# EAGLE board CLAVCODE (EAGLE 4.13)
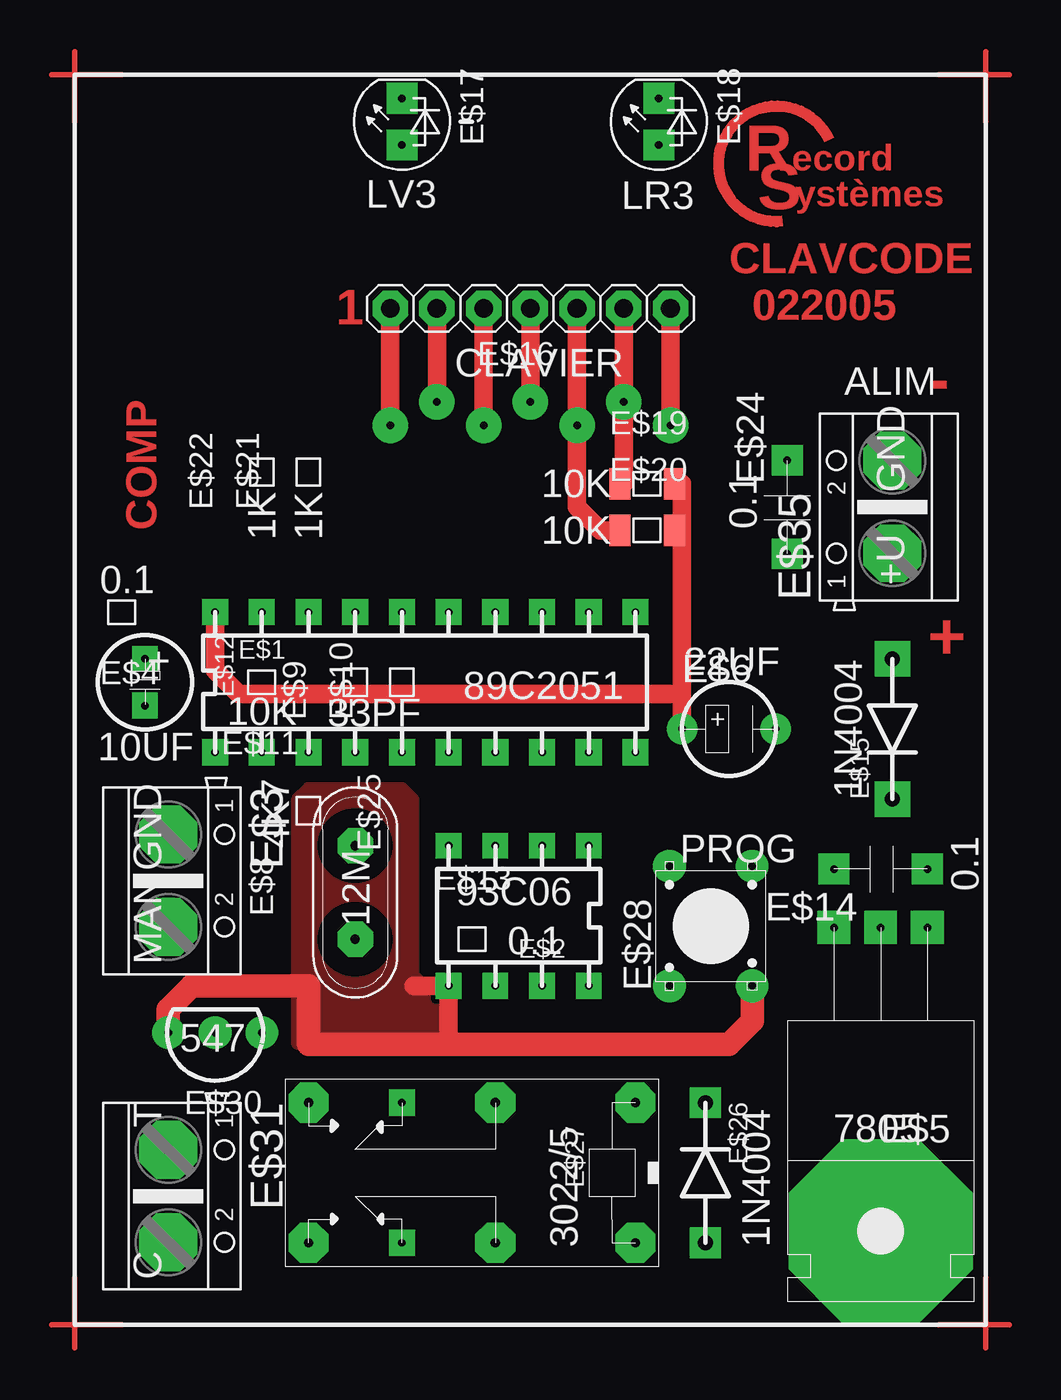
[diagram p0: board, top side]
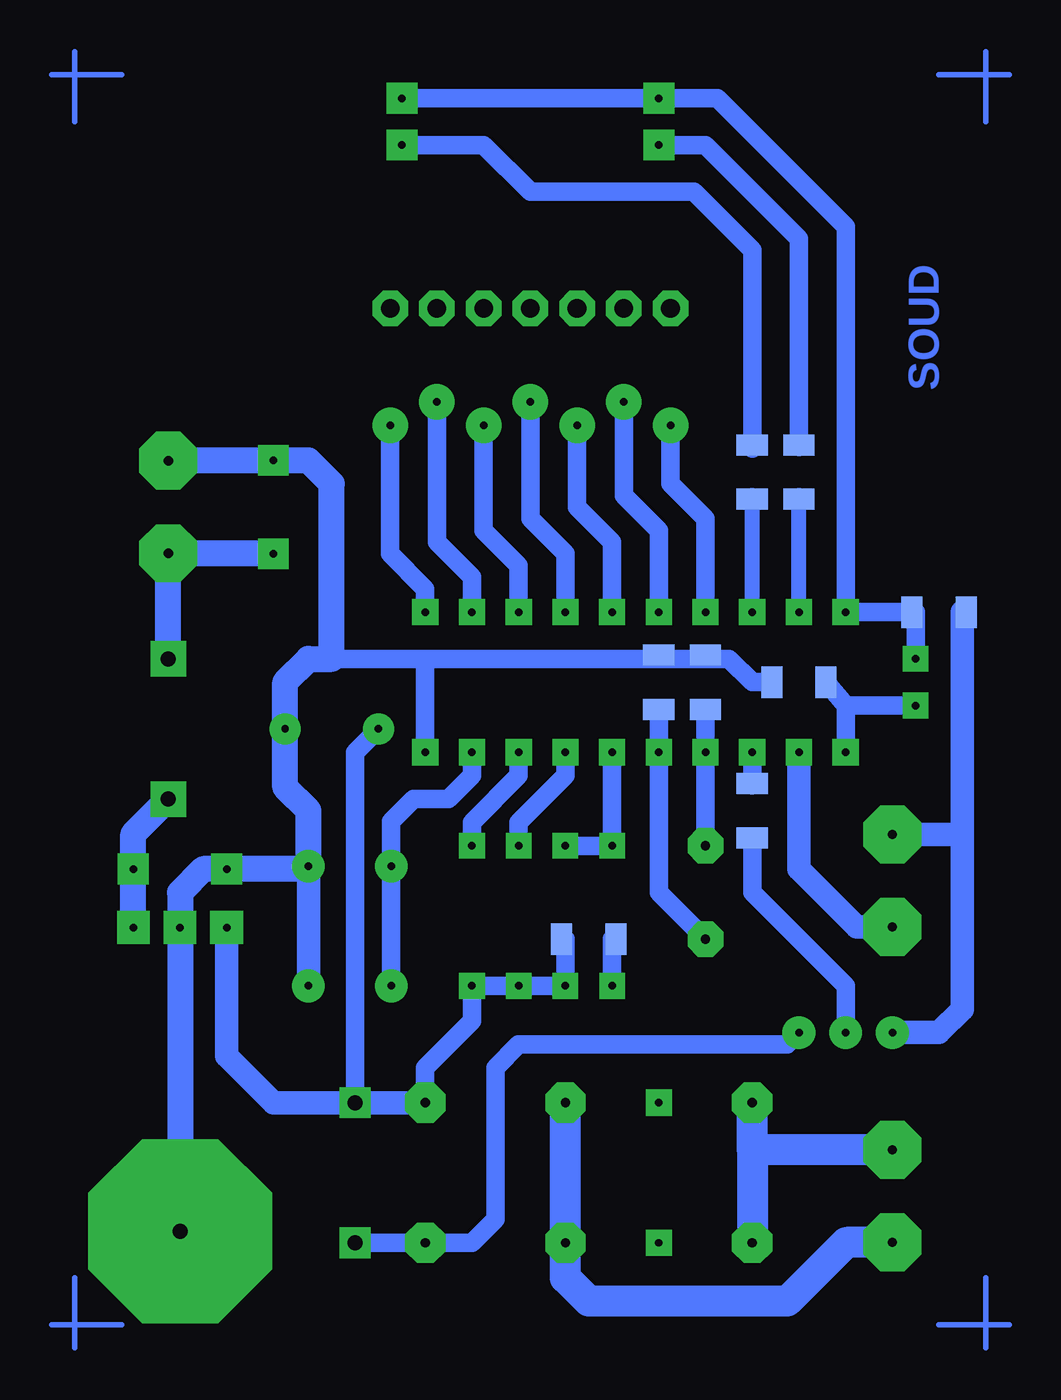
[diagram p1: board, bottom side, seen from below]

No outline drawn. Coordinates in mm, seen from the top.
Copper layers (1*16): Top 0.035mm / dielectric 1.5mm / Bottom 0.035mm
Design rules "default": minimum track width 0.3mm, minimum drill 0.4mm, track to track 0.1mm, track to pad 0.1mm, pad to pad 0.1mm, via to via 0.1mm, smd to smd 0.1mm, copper to edge 0.1mm, drill to drill 0.1mm, minimum pad ring 10mil, minimum via ring 8mil, stop-mask expansion 0mil, vias tented up to drill 0mil, thermal gap 10mil
Net classes: 0 signal: width 0.4 mm, drill 0.4 mm, clearance 0.4 mm; 1 siggros: width 0.8 mm, drill 0.6 mm, clearance 0.4 mm; 2 alim: width 1 mm, drill 1 mm, clearance 0.4 mm; 3 alimgros: width 1.27 mm, drill 1 mm, clearance 0.4 mm
tRestrict: area 13.3,24.1 to 17.1,27.9; area 13.3,19 to 17.1,22.9

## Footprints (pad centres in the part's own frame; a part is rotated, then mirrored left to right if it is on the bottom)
DIL20 = drill 0.406 pad 1.422 square: 1 0,0; 2 2.54,0; 3 5.08,0; 4 7.62,0; 5 10.16,0; 6 12.7,0; 7 15.24,0; 8 17.78,0; 9 20.32,0; 10 22.86,0; 11 22.86,7.62; 12 20.32,7.62; 13 17.78,7.62; 14 15.24,7.62; 15 12.7,7.62; 16 10.16,7.62; 17 7.62,7.62; 18 5.08,7.62; 19 2.54,7.62; 20 0,7.62
DIL8 = drill 0.406 pad 1.397 square: 1 0,0; 2 2.54,0; 3 5.08,0; 4 7.62,0; 5 7.62,7.62; 6 5.08,7.62; 7 2.54,7.62; 8 0,7.62
AK500/2 = drill 0.5 pad 3.15 octagon: 1 -2.515,0; 2 2.515,0
1206CU = smd 1.143 x 1.702 bottom: 1 -1.473,0; 2 1.473,0
78X = drill 0.406 pad 1.778 square: 1 0,0; 2 2.54,0; 3 5.08,0 | drill 0.813 pad 6.452 round: FIX 2.54,16.51
E5 = drill 0.406 pad 1.676 round: + 0,0; - 5.08,0
QS = drill 0.406 pad 1.676 octagon: 1 0,0; 2 5.08,0
E2,5 = drill 0.406 pad 1.397 square: + 0,0; - 2.54,0
C5 = drill 0.406 pad 1.676 square: 1 0,0; 2 5.08,0
D7,5 = drill 0.813 pad 1.676 square: A 7.62,0; K 0,0
1X07 = drill 1.016 pad 1.676 octagon: 1 -7.62,0; 2 -5.08,0; 3 -2.54,0; 4 0,0; 5 2.54,0; 6 5.08,0; 7 7.62,0
LED5VERT = drill 0.406 pad 1.676 square: A 0,0; K 0,2.54
1206 = smd 1.143 x 1.702: 1 -1.473,0; 2 1.473,0
OMRON = drill 0.406 pad 1.422 square: 1 0,0; 4 7.62,0; 6 12.7,0; 8 17.78,0; 9 17.78,7.62; 11 12.7,7.62; 13 7.62,7.62; 16 0,7.62
SECHOR = drill 0.406 pad 1.778 round: 1 0,0; 2 6.5,0; 3 6.5,4.5; 4 0,4.5
T1 = drill 0.406 pad 1.778 round: B 0,2.54; C 0,5.08; E 0,0

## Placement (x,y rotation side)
E$1  [DIL20]  7.62,31.11 0 top
E$2  [DIL8]  27.94,26.04 180 top
E$3  [AK500/2]  5.08,24.13 270 top
E$4  [1206CU]  2.54,38.73 180 top
E$5  [78X]  46.35,21.59 180 top
E$6  [E5]  33.02,32.38 0 top
E$7  [CORNER2]  0,0 180 top
E$8  [QS]  15.24,20.95 90 top
E$9  [1206CU]  15.24,34.92 90 top
E$10  [1206CU]  17.78,34.92 90 top
E$11  [1206CU]  10.16,34.92 180 top
E$12  [E2,5]  3.81,36.2 270 top
E$13  [1206CU]  21.59,20.95 0 top
E$14  [C5]  46.35,24.77 180 top
E$15  [D7,5]  44.45,28.57 90 top
E$16  [1X07]  24.77,55.24 180 top
E$17  [LED5VERT]  17.78,64.14 0 top
E$18  [LED5VERT]  31.75,64.14 0 top
E$19  [1206]  31.11,45.72 0 top
E$20  [1206]  31.11,43.18 0 top
E$21  [1206CU]  12.7,46.35 90 top
E$22  [1206CU]  10.16,46.35 90 top
E$23  [PRSCOMP]  47.62,60.96 0 top
E$24  [C5]  38.73,41.91 90 top
E$25  [1206CU]  12.7,27.94 270 top
E$26  [D7,5]  34.29,12.06 270 top
E$27  [OMRON]  30.48,12.06 180 top
E$28  [SECHOR]  36.83,18.41 90 top
E$29  [CORNER2]  49.53,0 270 top
E$30  [T1]  5.08,15.88 270 top
E$31  [AK500/2]  5.08,6.99 270 top
E$32  [CORNER2]  49.53,67.94 0 top
E$33  [CORNER2]  0,67.94 90 top
E$35  [AK500/2]  44.45,44.45 90 top

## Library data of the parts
E$1 E$2 E$5 E$6 E$8 E$12 E$14 E$15 E$17 E$18 E$23 E$24 E$26 E$27 E$30 = RECORD
E$3 E$31 E$35 = PTR500
E$4 E$9-E$11 E$13 E$19-E$22 E$25 = SMD
E$7 E$29 E$32 E$33 = MARKS
E$16 = PINHEAD
E$28 = KEY

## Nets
+5: E$1.20 E$2.6 E$2.7 E$2.8 E$4.1 E$5.3 E$6.+ E$12.+ E$13.2 E$17.K E$18.K E$19.2 E$20.2 E$26.K E$27.1
GND: E$1.10 E$2.5 E$3.1 E$4.2 E$5.2 E$5.FIX E$6.- E$9.2 E$10.2 E$11.1 E$13.1 E$14.2 E$24.2 E$28.1 E$28.2 E$30.E E$35.2
RST: E$1.1 E$11.2 E$12.-
S$1: E$1.4 E$8.2 E$9.1
S$2: E$1.5 E$8.1 E$10.1
S$3: E$1.2 E$3.2
S$6: E$1.6 E$2.3 E$2.4
S$7: E$1.7 E$2.2
S$8: E$1.8 E$2.1
S$9 [alimgros]: E$15.A E$24.1 E$35.1
S$12: E$1.17 E$16.7
S$13: E$1.16 E$16.6
S$14: E$1.15 E$16.5
S$15: E$1.14 E$16.4
S$16: E$1.13 E$16.3 E$20.1
S$17: E$1.12 E$16.2 E$19.1
S$18: E$1.11 E$16.1
S$20: E$1.18 E$21.1
S$21: E$1.19 E$22.1
S$22 [alimgros]: E$18.A E$21.2
S$23: E$17.A E$22.2
S$28: E$1.9 E$28.3 E$28.4
S$30: E$1.3 E$25.1
S$31: E$27.8 E$27.9 E$31.1
S$32: E$25.2 E$30.B
S$34 [alimgros]: E$5.1 E$14.1 E$15.K
S$35: E$26.A E$27.16 E$30.C
S$42: E$27.4 E$27.13 E$31.2

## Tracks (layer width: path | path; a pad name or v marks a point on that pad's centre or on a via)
+5
  Top 1.016: E$1.20 7.62,35.56 8.89,34.29 33.02,34.29 E$6.+ 33.02,43.18 | 33.02,43.18 E$20.2 | E$19.2 33.02,45.72 33.02,43.18
  Bottom 1.016: E$27.1 30.48,13.97 27.94,16.51 E$2.8 E$2.7 E$2.6 22.86,20.95 E$13.2 | E$6.+ 34.29,31.11 E$26.K | E$12.+ 3.81,38.73 E$4.1 E$1.20 7.62,59.69 14.61,66.67 E$17.K E$18.K
  Bottom 1.27: E$5.3 41.27,14.61 38.73,12.06 E$26.K E$27.1
GND
  Top 1.016: 20.32,15.24 E$2.5 18.41,18.41
  Top 1.27: E$28.1 36.83,16.51 35.56,15.24 20.32,15.24 12.7,15.24 12.7,18.41 6.35,18.41 5.08,17.14 E$30.E
  Bottom 0.61: E$11.1 11.43,34.92 | 15.24,36.2 E$9.2 | 17.78,36.2 E$10.2
  Bottom 1.016: E$11.1 12.7,34.92 13.97,36.2 15.24,36.2 17.78,36.2 30.48,36.2 | 30.48,36.2 E$1.10 | 35.56,36.2 30.48,36.2 | 1.27,38.73 E$4.2 | 36.83,24.77 E$28.2 | E$13.1 20.32,20.95 E$2.5 | 1.27,26.67 1.29,26.64
  Bottom 1.27: 1.27,38.73 1.27,26.67 1.27,17.14 2.54,15.88 E$30.E | E$28.1 36.83,24.77 | 1.29,26.64 E$3.1
  Bottom 1.422: E$5.FIX E$5.2 43.81,23.5 42.55,24.77 41.91,24.77 E$14.2 36.83,24.77 36.83,27.94 38.1,29.21 E$6.- 38.1,34.92 36.83,36.2 35.56,36.2 35.56,45.72 36.83,46.99 E$24.2 38.76,46.97 E$35.2
  pour Top: 12.7,29.21 17.78,29.21 18.41,28.57 18.41,19.05 19.05,18.41 20.32,18.41 20.32,15.24 12.06,15.24 12.06,28.57
RST
  Bottom 0.61: E$11.2 8.89,34.92
  Bottom 1.016: 7.62,33.66 E$1.1 | 7.62,33.66 E$11.2 | E$12.- 7.62,33.66
S$1
  Bottom 1.016: E$9.1 E$1.4 E$8.2
S$2
  Bottom 1.016: E$10.1 E$1.5 17.78,23.5 E$8.1
S$3
  Bottom 1.27: E$3.2 7.01,21.61 10.16,24.77 E$1.2
S$4  (via drill 0.5 pad 1.93)
  other vias: 17.14,55.24
S$5  (via drill 0.41 pad 1.68)
  other vias: 17.14,55.24
S$6
  Bottom 1.016: E$1.6 E$2.4 E$2.3
S$7
  Bottom 1.016: E$2.2 25.4,27.3 22.86,29.84 E$1.7
S$8
  Bottom 1.016: E$2.1 27.94,27.3 25.4,29.84 E$1.8
S$9
  Bottom 1.422: E$24.1 38.76,41.94 E$35.1 E$15.A
S$10  (via drill 0.41 pad 1.68)
  other vias: 19.68,55.24
S$11  (via drill 0.41 pad 1.68)
  other vias: 34.29,4.45
S$12  (via drill 0.41 pad 1.93)
  Top 1.016: v17.14,48.9 E$16.7
  Bottom 1.016: E$1.17 15.24,43.81 17.14,45.72 v17.14,48.9
S$13  (via drill 0.41 pad 1.93)
  Top 1.016: v19.68,50.16 E$16.6
  Bottom 1.016: E$1.16 17.78,43.18 19.68,45.09 v19.68,50.16
S$14  (via drill 0.41 pad 1.93)
  Top 1.016: v22.23,48.9 E$16.5
  Bottom 1.016: E$1.15 20.32,42.55 22.23,44.45 v22.23,48.9
S$15  (via drill 0.41 pad 1.93)
  Top 1.016: v24.77,50.16 E$16.4
  Bottom 1.016: E$1.14 22.86,41.91 24.77,43.81 v24.77,50.16
S$16  (via drill 0.41 pad 1.93)
  Top 1.016: E$16.3 v27.3,48.9 27.3,44.45 28.57,43.18 E$20.1
  Bottom 1.016: E$1.13 25.4,41.27 27.3,43.18 v27.3,48.9
S$17  (via drill 0.41 pad 1.93)
  Top 1.016: E$16.2 v29.84,50.16 29.84,45.72 E$19.1
  Bottom 1.016: E$1.12 27.94,40.64 29.84,42.55 v29.84,50.16
S$18  (via drill 0.41 pad 1.93)
  Top 1.016: v32.38,48.9 E$16.1
  Bottom 1.016: E$1.11 30.48,40.01 32.38,41.91 v32.38,48.9
S$19  (via drill 0.41 pad 1.68)
  other vias: 22.23,55.24
S$20
  Bottom 0.813: 12.7,45.09 E$21.1 E$1.18
S$21
  Bottom 0.813: 10.16,45.09 E$22.1 E$1.19
S$22
  Bottom 1.016: E$18.A 27.3,64.14 24.77,61.59 15.88,61.59 12.7,58.42 E$21.2 12.7,47.62
S$23
  Bottom 0.813: E$22.2 10.16,47.62
  Bottom 1.016: E$17.A 15.24,64.14 10.16,59.05 E$22.2
S$24  (via drill 0.41 pad 1.68)
  other vias: 24.77,55.24
S$25  (via drill 0.41 pad 1.68)
  other vias: 27.3,55.24
S$26  (via drill 0.41 pad 1.68)
  other vias: 29.84,55.24
S$27  (via drill 0.41 pad 1.68)
  other vias: 32.38,55.24
S$28
  Bottom 1.016: E$1.9 27.94,29.84 29.21,28.57 31.11,28.57 32.33,27.36 E$28.3 32.33,24.82 32.38,24.77 32.33,24.71 E$28.4
S$29  (via drill 0.5 pad 1.93)
  other vias: 44.45,28.57
S$30
  Bottom 0.813: E$25.1 12.7,29.21
  Bottom 1.016: E$25.1 E$1.3
S$31
  Bottom 1.27: 12.68,9.5 12.7,9.53
  Bottom 1.676: E$27.9 12.7,9.53 E$27.8 | E$31.1 12.68,9.5
S$32
  Bottom 1.016: E$25.2 12.7,23.5 7.62,18.41 E$30.B
S$33  (via drill 0.5 pad 2.18)
  other vias: 12.7,4.45
S$34
  Bottom 1.422: E$15.K 46.35,26.67 E$14.1 46.35,24.13 E$5.1
S$35
  Bottom 1.016: E$26.A E$27.16 27.94,4.45 26.67,5.71 26.67,13.97 25.4,15.24 10.79,15.24 E$30.C
S$36  (via drill 0.5 pad 1.93)
  other vias: 44.45,36.2
S$37  (via drill 0.41 pad 1.68)
  other vias: 34.29,12.06
S$38  (via drill 0.5 pad 1.93)
  other vias: 19.68,55.24
S$39  (via drill 0.5 pad 1.93)
  other vias: 22.23,55.24
S$40  (via drill 0.5 pad 1.93)
  other vias: 24.77,55.24
S$41  (via drill 0.5 pad 1.93)
  other vias: 27.3,55.24
S$42
  Bottom 1.676: E$27.4 E$27.13 22.86,2.54 21.59,1.27 10.79,1.27 7.59,4.47 E$31.2
S$43  (via drill 0.5 pad 1.93)
  other vias: 29.84,55.24
S$44  (via drill 0.5 pad 1.93)
  other vias: 32.38,55.24
S$45  (via drill 0.5 pad 2.18)
  other vias: 22.86,12.06
S$46  (via drill 0.5 pad 2.18)
  other vias: 22.86,4.45
S$47  (via drill 0.5 pad 2.18)
  other vias: 12.7,12.06
S$48  (via drill 0.5 pad 2.18)
  other vias: 30.48,12.06
S$49  (via drill 0.5 pad 2.18)
  other vias: 30.48,4.45
S$50  (via drill 0.5 pad 10)
  other vias: 43.81,5.08
S$51  (via drill 0.5 pad 1.93)
  other vias: 15.24,26.04
S$52  (via drill 0.5 pad 1.93)
  other vias: 15.24,20.95

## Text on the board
Top: CLAVCODE | 022005 | 1 | - | COMP | +
Bottom: SOUD
tPlace: LV3 | LR3 | CLAVIER | ALIM | 10K | GND | 1K | 1K | 0.1 | 10K | 0.1 | +U | 22UF | 89C2051 | 10K | 33PF | 10UF | 1N4004 | 4K7 | GND | PROG | 0.1 | 93C06 | 12M | MAN | 0.1 | 547 | T | 7805 | 3022/5 | 1N4004 | C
